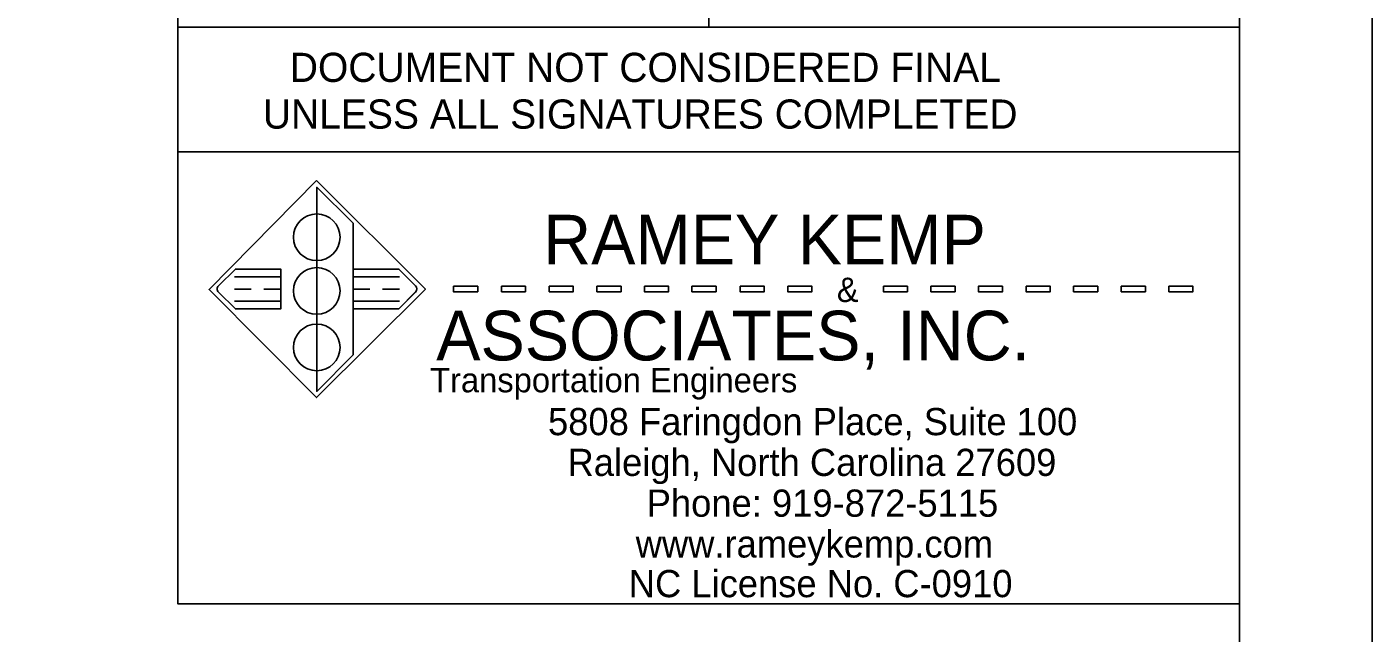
# Model space of a CAD drawing. Extents: x 573078 to 573116.6, y -55221.3 to -55199.3.
# Drawn here: x 573106.94 to 573112.01, y -55204.83 to -55202.55 of the extents above; entities that cross this region are included whole.
import ezdxf

# ---------------------------------------------------------------- set-up
doc = ezdxf.new("R2010")
doc.units = 0
for name, color, linetype in [('Old_Level_2', 7, 'Continuous'), ('Old_Level_4', 7, 'Continuous'), ('Sheet Plan CELL', 7, 'Continuous'), ('Sheet Plot Border Inside CELL', 7, 'Continuous'), ('Sheet Sticker Exception Certification CELL', 7, 'Continuous')]:
    doc.layers.add(name, color=color, linetype=linetype)

msp = doc.modelspace()

# ---------------------------------------------------------------- linework, layer by layer
at = {"layer": 'Old_Level_2'}
for p, q in [((573108.0362, -55203.154), (573108.0362, -55203.9231)), ((573108.0362, -55203.154), (573108.1731, -55203.2894)), ((573108.1731, -55203.2894), (573108.1731, -55203.7856)), ((573107.7299, -55203.4625), (573107.666, -55203.5254)), ((573107.9008, -55203.4625), (573107.7299, -55203.4625)), ((573107.9008, -55203.4625), (573107.9008, -55203.6124)), ((573108.1731, -55203.4625), (573108.3461, -55203.4625)), ((573108.3461, -55203.4625), (573108.409, -55203.5259)), ((573107.7299, -55203.6117), (573107.666, -55203.5488)), ((573108.3461, -55203.6118), (573108.409, -55203.5484)), ((573107.9008, -55203.6117), (573107.7299, -55203.6117)), ((573107.9008, -55203.6124), (573107.7299, -55203.6124)), ((573108.1731, -55203.6118), (573108.3461, -55203.6118)), ((573108.0362, -55203.9231), (573108.1731, -55203.7856))]:
    msp.add_line(p, q, dxfattribs=at)
for points in [[(573108.0362, -55203.8452), (573108.0362, -55203.9231), (573108.1731, -55203.7856), (573108.1731, -55203.5835), (573108.1731, -55203.5373), (573108.1731, -55203.4917), (573108.1731, -55203.2894), (573108.0362, -55203.154), (573108.0362, -55203.2545)], [(573108.0362, -55203.4303), (573108.0362, -55203.2545)], [(573107.9008, -55203.5835), (573107.9008, -55203.5373), (573107.9008, -55203.4917), (573107.9008, -55203.4625), (573107.7299, -55203.4625), (573107.666, -55203.5254)], [(573108.0362, -55203.4303), (573108.0362, -55203.4564)], [(573108.0362, -55203.6321), (573108.0362, -55203.4564)], [(573108.4087, -55203.5256), (573108.3461, -55203.4625), (573108.1731, -55203.4625), (573108.1731, -55203.4917), (573108.1731, -55203.5373), (573108.1731, -55203.5835)], [(573107.666, -55203.5488), (573107.7299, -55203.6124), (573107.9008, -55203.6124), (573107.9008, -55203.5835)], [(573108.1731, -55203.5835), (573108.1731, -55203.6118), (573108.3461, -55203.6118), (573108.4087, -55203.5487)], [(573108.5514, -55203.5268), (573108.5514, -55203.5478), (573108.6429, -55203.5478), (573108.6429, -55203.5268), (573108.5514, -55203.5268)], [(573108.7328, -55203.5268), (573108.7328, -55203.5478), (573108.8227, -55203.5478), (573108.8227, -55203.5268), (573108.7328, -55203.5268)], [(573108.9124, -55203.5268), (573108.9124, -55203.5478), (573109.0033, -55203.5478), (573109.0033, -55203.5268), (573108.9124, -55203.5268)], [(573109.0924, -55203.5268), (573109.0924, -55203.5478), (573109.1832, -55203.5478), (573109.1832, -55203.5268), (573109.0924, -55203.5268)], [(573109.2715, -55203.5268), (573109.2715, -55203.5478), (573109.3625, -55203.5478), (573109.3625, -55203.5268), (573109.2715, -55203.5268)], [(573109.4506, -55203.5268), (573109.4506, -55203.5478), (573109.5416, -55203.5478), (573109.5416, -55203.5268), (573109.4506, -55203.5268)], [(573109.6319, -55203.5268), (573109.6319, -55203.5478), (573109.7232, -55203.5478), (573109.7232, -55203.5268), (573109.6319, -55203.5268)], [(573109.8116, -55203.5268), (573109.8116, -55203.5478), (573109.9027, -55203.5478), (573109.9027, -55203.5268), (573109.8116, -55203.5268)], [(573110.1721, -55203.5268), (573110.1721, -55203.5478), (573110.2628, -55203.5478), (573110.2628, -55203.5268), (573110.1721, -55203.5268)], [(573110.3512, -55203.5268), (573110.3512, -55203.5478), (573110.4421, -55203.5478), (573110.4421, -55203.5268), (573110.3512, -55203.5268)], [(573110.6215, -55203.5268), (573110.5305, -55203.5268), (573110.5305, -55203.5478), (573110.6215, -55203.5478), (573110.6215, -55203.5268)], [(573110.7099, -55203.5268), (573110.7099, -55203.5478), (573110.8009, -55203.5478), (573110.8009, -55203.5268), (573110.7099, -55203.5268)], [(573110.8893, -55203.5268), (573110.8893, -55203.5478), (573110.9803, -55203.5478), (573110.9803, -55203.5268), (573110.8893, -55203.5268)], [(573111.0687, -55203.5268), (573111.0687, -55203.5478), (573111.1597, -55203.5478), (573111.1597, -55203.5268), (573111.0687, -55203.5268)], [(573111.2481, -55203.5478), (573111.339, -55203.5478), (573111.339, -55203.5268), (573111.2481, -55203.5268), (573111.2481, -55203.5478)], [(573108.0362, -55203.6321), (573108.0362, -55203.6695)], [(573108.0362, -55203.8452), (573108.0362, -55203.6695)]]:
    msp.add_lwpolyline(points, dxfattribs=at)
for centre, radius, start, end in [((573108.0362, -55203.3424), 0.0879, 90, 180), ((573108.0362, -55203.3424), 0.0879, 0, 90), ((573108.0362, -55203.3424), 0.0879, 180, 270), ((573108.0362, -55203.3424), 0.0879, 270, 0), ((573108.0362, -55203.5443), 0.0879, 90, 180), ((573108.0362, -55203.5443), 0.0879, 0, 90), ((573107.6775, -55203.5371), 0.0164, 134.5812, 225.4188), ((573107.6775, -55203.5371), 0.0164, 134.5812, 225.4188), ((573108.0362, -55203.5443), 0.0879, 180, 270), ((573108.0362, -55203.5443), 0.0879, 270, 0), ((573108.3971, -55203.5371), 0.0164, 315.2131, 44.7869), ((573108.3971, -55203.5371), 0.0164, 315.2131, 44.7869), ((573108.0362, -55203.7574), 0.0879, 90, 180), ((573108.0362, -55203.7574), 0.0879, 0, 90), ((573108.0362, -55203.7574), 0.0879, 180, 270), ((573108.0362, -55203.7574), 0.0879, 270, 0)]:
    msp.add_arc(centre, radius, start, end, dxfattribs=at)
at = {"layer": 'Old_Level_4'}
for p, q in [((573108.0353, -55203.1289), (573107.6305, -55203.5397)), ((573108.0353, -55203.1289), (573108.446, -55203.5377)), ((573107.9008, -55203.4917), (573107.7257, -55203.4917)), ((573108.3485, -55203.4917), (573108.1735, -55203.4917)), ((573108.0353, -55203.9465), (573107.6305, -55203.5397)), ((573107.789, -55203.5373), (573107.7257, -55203.5373)), ((573107.9008, -55203.5373), (573107.8369, -55203.5373)), ((573108.446, -55203.5377), (573108.0353, -55203.9465)), ((573108.2368, -55203.5373), (573108.1735, -55203.5373)), ((573108.3485, -55203.5373), (573108.2846, -55203.5373)), ((573110.5305, -55203.5478), (573110.5305, -55203.5268)), ((573110.6215, -55203.5268), (573110.5305, -55203.5268)), ((573110.5305, -55203.5478), (573110.6215, -55203.5478)), ((573110.6215, -55203.5478), (573110.6215, -55203.5268)), ((573111.2481, -55203.5478), (573111.2481, -55203.5268)), ((573111.2481, -55203.5268), (573111.339, -55203.5268)), ((573111.2481, -55203.5478), (573111.339, -55203.5478)), ((573111.339, -55203.5478), (573111.339, -55203.5268)), ((573107.9008, -55203.5835), (573107.7257, -55203.5835)), ((573108.3485, -55203.5835), (573108.1735, -55203.5835))]:
    msp.add_line(p, q, dxfattribs=at)
for points in [[(573108.0353, -55203.1289), (573107.6305, -55203.5397), (573108.0353, -55203.9465), (573108.446, -55203.5377), (573108.0353, -55203.1289)], [(573108.0362, -55203.2545), (573108.0362, -55203.4303)], [(573108.0362, -55203.4564), (573108.0362, -55203.6321)], [(573108.0362, -55203.6695), (573108.0362, -55203.8452)]]:
    msp.add_lwpolyline(points, dxfattribs=at)
for points in [[(573108.5514, -55203.5268), (573108.6429, -55203.5268), (573108.6429, -55203.5478), (573108.5514, -55203.5478)], [(573108.7328, -55203.5268), (573108.8227, -55203.5268), (573108.8227, -55203.5478), (573108.7328, -55203.5478)], [(573108.9124, -55203.5268), (573109.0033, -55203.5268), (573109.0033, -55203.5478), (573108.9124, -55203.5478)], [(573109.0924, -55203.5268), (573109.1832, -55203.5268), (573109.1832, -55203.5478), (573109.0924, -55203.5478)], [(573109.2715, -55203.5268), (573109.3625, -55203.5268), (573109.3625, -55203.5478), (573109.2715, -55203.5478)], [(573109.4506, -55203.5268), (573109.5416, -55203.5268), (573109.5416, -55203.5478), (573109.4506, -55203.5478)], [(573109.6319, -55203.5268), (573109.7232, -55203.5268), (573109.7232, -55203.5478), (573109.6319, -55203.5478)], [(573109.8116, -55203.5268), (573109.9027, -55203.5268), (573109.9027, -55203.5478), (573109.8116, -55203.5478)], [(573110.1721, -55203.5268), (573110.2628, -55203.5268), (573110.2628, -55203.5478), (573110.1721, -55203.5478)], [(573110.3512, -55203.5268), (573110.4421, -55203.5268), (573110.4421, -55203.5478), (573110.3512, -55203.5478)], [(573110.7099, -55203.5268), (573110.8009, -55203.5268), (573110.8009, -55203.5478), (573110.7099, -55203.5478)], [(573110.8893, -55203.5268), (573110.9803, -55203.5268), (573110.9803, -55203.5478), (573110.8893, -55203.5478)], [(573111.0687, -55203.5268), (573111.1597, -55203.5268), (573111.1597, -55203.5478), (573111.0687, -55203.5478)]]:
    msp.add_lwpolyline(points, close=True, dxfattribs=at)
for centre in [(573108.0362, -55203.3424), (573108.0362, -55203.5443), (573108.0362, -55203.7574)]:
    msp.add_circle(centre, 0.0879, dxfattribs=at)
for centre, start, end in [((573108.0362, -55203.3424), 0, 90), ((573108.0362, -55203.3424), 270, 0), ((573108.0362, -55203.5443), 0, 90), ((573108.0362, -55203.5443), 270, 0), ((573108.0362, -55203.7574), 0, 90), ((573108.0362, -55203.7574), 270, 0)]:
    msp.add_arc(centre, 0.0879, start, end, dxfattribs=at)
at = {"layer": 'Sheet Plan CELL'}
msp.add_line((573107.5132, -55203.0202), (573107.5132, -55204.2569), dxfattribs=at)
for points in [[(573081.5142, -55199.7984), (573111.5142, -55199.7984), (573111.5142, -55220.7984), (573081.5142, -55220.7984)], [(573109.5142, -55200.3002), (573107.5132, -55200.3002), (573107.5132, -55202.5502), (573109.5142, -55202.5502)], [(573109.5142, -55200.3002), (573111.5142, -55200.3002), (573111.5142, -55202.5502), (573109.5142, -55202.5502)], [(573111.5139, -55204.7237), (573107.5132, -55204.7237), (573107.5132, -55203.0202), (573111.5139, -55203.0202)]]:
    msp.add_lwpolyline(points, close=True, dxfattribs=at)
at = {"layer": 'Sheet Plot Border Inside CELL'}
msp.add_lwpolyline([(573112.0142, -55199.2984), (573078.0142, -55199.2984), (573078.0142, -55221.2984), (573112.0142, -55221.2984)], close=True, dxfattribs=at)
at = {"layer": 'Sheet Sticker Exception Certification CELL'}
for p, q in [((573107.5132, -55203.0202), (573107.5132, -55202.5502)), ((573107.5132, -55202.5502), (573111.5139, -55202.5502)), ((573111.5139, -55202.5502), (573111.5139, -55203.0202)), ((573111.5139, -55203.0202), (573107.5132, -55203.0202))]:
    msp.add_line(p, q, dxfattribs=at)

# ---------------------------------------------------------------- texts
at = {"layer": 'Old_Level_4'}
for s, height, p in [('RAMEY KEMP', 0.18711, (573108.89, -55203.4449)), ('&', 0.0919, (573109.9967, -55203.5862)), ('ASSOCIATES, INC.', 0.187109, (573108.4867, -55203.8063)), ('Transportation Engineers', 0.092176, (573108.4635, -55203.9265)), ('5808 Faringdon Place, Suite 100', 0.102418, (573108.908, -55204.0881)), ('Raleigh, North Carolina 27609', 0.102418, (573108.9816, -55204.2417)), ('Phone: 919-872-5115 ', 0.102418, (573109.28, -55204.3953)), ('www.rameykemp.com', 0.102418, (573109.2385, -55204.549)), ('NC License No. C-0910', 0.102418, (573109.2125, -55204.6985))]:
    msp.add_text(s, height=height, dxfattribs=at).set_placement(p)
at = {"layer": 'Sheet Sticker Exception Certification CELL'}
for s, p in [('DOCUMENT NOT CONSIDERED FINAL', (573107.9346, -55202.7571)), ('UNLESS ALL SIGNATURES COMPLETED', (573107.8332, -55202.9331))]:
    msp.add_text(s, height=0.11, dxfattribs=at).set_placement(p)

doc.saveas('drawing.dxf')
